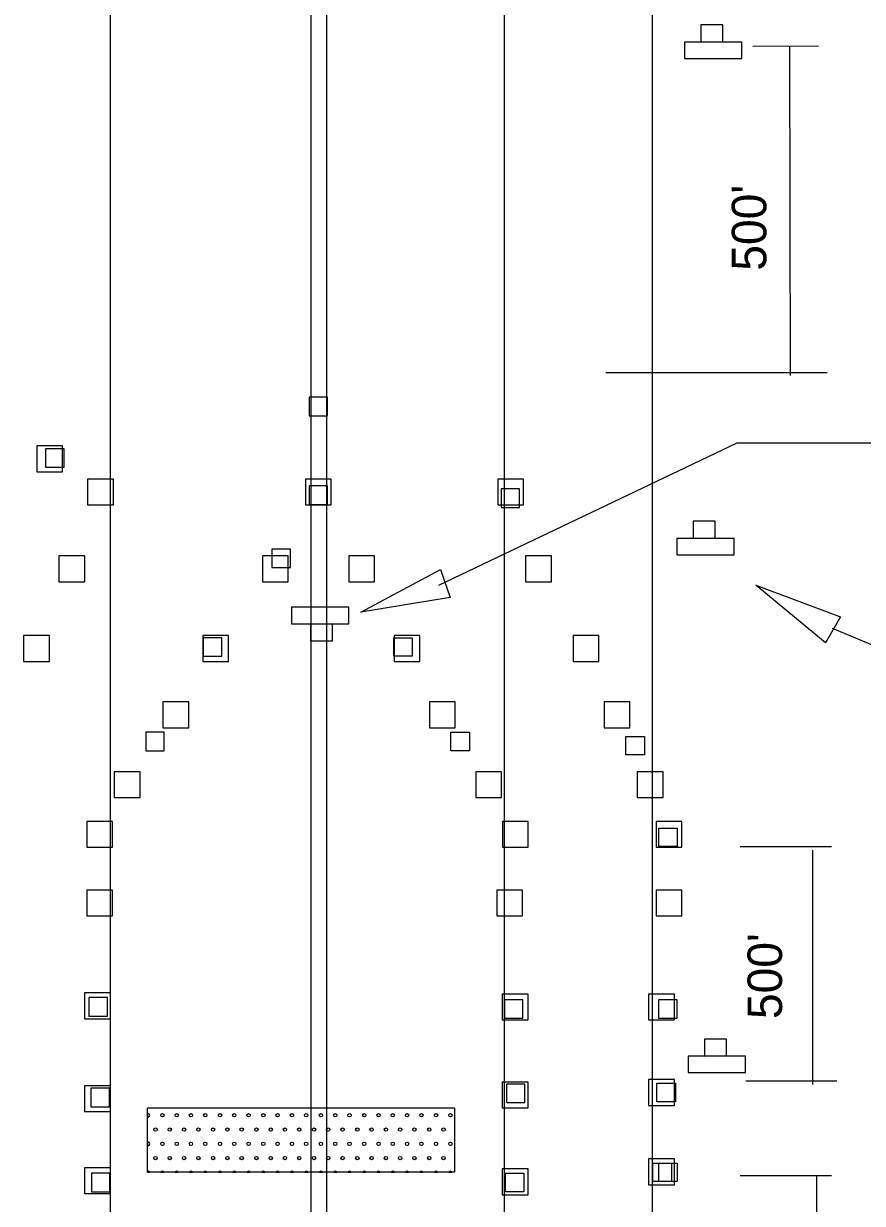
# Model space of a CAD drawing. Extents: x 1531.35 to 1538.58, y 1529.59 to 1539.23.
# Drawn here: x 1535.351 to 1536.808, y 1535.34 to 1537.39 of the extents above; entities that cross this region are included whole.
import ezdxf

# ---------------------------------------------------------------- set-up
doc = ezdxf.new("R2010")
doc.units = 0
for name, color, linetype in [('DETL-DIMS', 7, 'Continuous'), ('DETL-LINE', 7, 'Continuous'), ('DETL-NOTE', 7, 'Continuous'), ('USER-BORD', 7, 'Continuous')]:
    doc.layers.add(name, color=color, linetype=linetype)

# ---------------------------------------------------------------- blocks, each defined once
blk = doc.blocks.new('CD20')
at = {"layer": 'USER-BORD'}
blk.add_lwpolyline([(-0.0625, -0.0625), (0, -0.0625), (0, 0), (-0.0625, 0)], close=True, dxfattribs=at)
blk = doc.blocks.new('SIGN13')
at = {"layer": 'USER-BORD'}
for points in [[(-0.0134, 0.0182), (0.011, 0.0189), (0.011, 0.0371), (-0.0134, 0.0371)], [(-0.0314, 0.0182), (-0.0314, 0), (0.032, 0), (0.032, 0.0182)]]:
    blk.add_lwpolyline(points, close=True, dxfattribs=at)

msp = doc.modelspace()

# ---------------------------------------------------------------- linework, layer by layer
at = {"layer": 'DETL-DIMS'}
for p, q in [((1536.6173, 1537.3504), (1536.7316, 1537.3506)), ((1536.6829, 1536.7781), (1536.6818, 1537.3505)), ((1536.7465, 1536.7827), (1536.3621, 1536.7827)), ((1536.0721, 1536.4139), (1536.5902, 1536.6615)), ((1536.5902, 1536.6615), (1536.8925, 1536.6616)), ((1536.755, 1536.3393), (1537.0765, 1536.2049)), ((1536.5957, 1535.9605), (1536.7538, 1535.9605)), ((1536.7218, 1535.5467), (1536.7218, 1535.9538)), ((1536.6055, 1535.5534), (1536.7635, 1535.5534)), ((1536.5957, 1535.3886), (1536.7538, 1535.3886)), ((1536.7279, 1535.3886), (1536.7279, 1533.0756))]:
    msp.add_line(p, q, dxfattribs=at)
for points in [[(1536.0754, 1536.4414), (1536.0919, 1536.3925), (1535.9368, 1536.3672)], [(1536.7694, 1536.3589), (1536.7436, 1536.3141), (1536.6224, 1536.4141)]]:
    msp.add_lwpolyline(points, close=True, dxfattribs=at)
at = {"layer": 'DETL-LINE'}
for p, q in [((1536.1857, 1538.9058), (1536.1857, 1535.6352)), ((1535.5016, 1538.8924), (1535.5016, 1531.7496)), ((1535.8503, 1538.8924), (1535.8503, 1531.7496)), ((1535.8772, 1538.8924), (1535.8772, 1531.7496)), ((1536.4426, 1538.8924), (1536.4426, 1531.7496)), ((1536.1857, 1535.6352), (1536.1857, 1531.763)), ((1535.5667, 1535.3947), (1535.5667, 1535.5057)), ((1536.0994, 1535.5057), (1535.5667, 1535.5057)), ((1535.5667, 1535.3947), (1535.5667, 1535.5057)), ((1536.0994, 1535.5057), (1535.5667, 1535.5057)), ((1535.5676, 1535.4934), (1535.5676, 1535.4934)), ((1535.5924, 1535.4934), (1535.5924, 1535.4934)), ((1535.6172, 1535.4934), (1535.6172, 1535.4934)), ((1535.642, 1535.4934), (1535.642, 1535.4934)), ((1535.6668, 1535.4934), (1535.6668, 1535.4934)), ((1535.6924, 1535.4934), (1535.6924, 1535.4934)), ((1535.7172, 1535.4934), (1535.7172, 1535.4934)), ((1535.742, 1535.4934), (1535.742, 1535.4934)), ((1535.7676, 1535.4934), (1535.7676, 1535.4934)), ((1535.7924, 1535.4934), (1535.7924, 1535.4934)), ((1535.8172, 1535.4934), (1535.8172, 1535.4934)), ((1535.842, 1535.4934), (1535.842, 1535.4934)), ((1535.8676, 1535.4934), (1535.8676, 1535.4934)), ((1535.8924, 1535.4934), (1535.8924, 1535.4934)), ((1535.9172, 1535.4934), (1535.9172, 1535.4934)), ((1535.9428, 1535.4934), (1535.9428, 1535.4934)), ((1535.9676, 1535.4934), (1535.9676, 1535.4934)), ((1535.9924, 1535.4934), (1535.9924, 1535.4934)), ((1536.0172, 1535.4934), (1536.0172, 1535.4934)), ((1536.042, 1535.4934), (1536.042, 1535.4934)), ((1536.0676, 1535.4934), (1536.0676, 1535.4934)), ((1536.0924, 1535.4934), (1536.0924, 1535.4934)), ((1536.0994, 1535.5057), (1536.0994, 1535.3947)), ((1536.0994, 1535.5057), (1536.0994, 1535.3947)), ((1535.5796, 1535.4686), (1535.5796, 1535.4686)), ((1535.5804, 1535.4686), (1535.5804, 1535.4686)), ((1535.6044, 1535.4686), (1535.6044, 1535.4686)), ((1535.6052, 1535.4686), (1535.6052, 1535.4686)), ((1535.63, 1535.4686), (1535.63, 1535.4686)), ((1535.63, 1535.4686), (1535.63, 1535.4686)), ((1535.6548, 1535.4686), (1535.6548, 1535.4686)), ((1535.6548, 1535.4686), (1535.6548, 1535.4686)), ((1535.6796, 1535.4686), (1535.6796, 1535.4686)), ((1535.6804, 1535.4686), (1535.6804, 1535.4686)), ((1535.7044, 1535.4686), (1535.7044, 1535.4686)), ((1535.7052, 1535.4686), (1535.7052, 1535.4686)), ((1535.73, 1535.4686), (1535.73, 1535.4686)), ((1535.73, 1535.4686), (1535.73, 1535.4686)), ((1535.7548, 1535.4686), (1535.7548, 1535.4686)), ((1535.7556, 1535.4686), (1535.7556, 1535.4686)), ((1535.7796, 1535.4686), (1535.7796, 1535.4686)), ((1535.7804, 1535.4686), (1535.7804, 1535.4686)), ((1535.8044, 1535.4686), (1535.8044, 1535.4686)), ((1535.8052, 1535.4686), (1535.8052, 1535.4686)), ((1535.83, 1535.4686), (1535.83, 1535.4686)), ((1535.83, 1535.4686), (1535.83, 1535.4686)), ((1535.8548, 1535.4686), (1535.8548, 1535.4686)), ((1535.8556, 1535.4686), (1535.8556, 1535.4686)), ((1535.8796, 1535.4686), (1535.8796, 1535.4686)), ((1535.8804, 1535.4686), (1535.8804, 1535.4686)), ((1535.9052, 1535.4686), (1535.9052, 1535.4686)), ((1535.9052, 1535.4686), (1535.9052, 1535.4686)), ((1535.93, 1535.4686), (1535.93, 1535.4686)), ((1535.9308, 1535.4686), (1535.9308, 1535.4686)), ((1535.9548, 1535.4686), (1535.9548, 1535.4686)), ((1535.9556, 1535.4686), (1535.9556, 1535.4686)), ((1535.9796, 1535.4686), (1535.9796, 1535.4686)), ((1535.9804, 1535.4686), (1535.9804, 1535.4686)), ((1536.0052, 1535.4686), (1536.0052, 1535.4686)), ((1536.0052, 1535.4686), (1536.0052, 1535.4686)), ((1536.03, 1535.4686), (1536.03, 1535.4686)), ((1536.03, 1535.4686), (1536.03, 1535.4686)), ((1536.0548, 1535.4686), (1536.0548, 1535.4686)), ((1536.0556, 1535.4686), (1536.0556, 1535.4686)), ((1536.0796, 1535.4686), (1536.0796, 1535.4686)), ((1536.0804, 1535.4686), (1536.0804, 1535.4686)), ((1535.5676, 1535.4438), (1535.5676, 1535.4438)), ((1535.5676, 1535.4438), (1535.5676, 1535.4438)), ((1535.5924, 1535.4438), (1535.5924, 1535.4438)), ((1535.5924, 1535.4438), (1535.5924, 1535.4438)), ((1535.6172, 1535.4438), (1535.6172, 1535.4438)), ((1535.6172, 1535.4438), (1535.6172, 1535.4438)), ((1535.642, 1535.4438), (1535.642, 1535.4438)), ((1535.642, 1535.4438), (1535.642, 1535.4438)), ((1535.6668, 1535.4438), (1535.6668, 1535.4438)), ((1535.6668, 1535.4438), (1535.6668, 1535.4438)), ((1535.6924, 1535.4438), (1535.6924, 1535.4438)), ((1535.6924, 1535.4438), (1535.6924, 1535.4438)), ((1535.7172, 1535.4438), (1535.7172, 1535.4438)), ((1535.7172, 1535.4438), (1535.7172, 1535.4438)), ((1535.742, 1535.4438), (1535.742, 1535.4438)), ((1535.742, 1535.4438), (1535.742, 1535.4438)), ((1535.7676, 1535.4438), (1535.7676, 1535.4438)), ((1535.7676, 1535.4438), (1535.7676, 1535.4438)), ((1535.7924, 1535.4438), (1535.7924, 1535.4438)), ((1535.7924, 1535.4438), (1535.7924, 1535.4438)), ((1535.8172, 1535.4438), (1535.8172, 1535.4438)), ((1535.8172, 1535.4438), (1535.8172, 1535.4438)), ((1535.842, 1535.4438), (1535.842, 1535.4438)), ((1535.842, 1535.4438), (1535.842, 1535.4438)), ((1535.8676, 1535.4438), (1535.8676, 1535.4438)), ((1535.8676, 1535.4438), (1535.8676, 1535.4438)), ((1535.8924, 1535.4438), (1535.8924, 1535.4438)), ((1535.8924, 1535.4438), (1535.8924, 1535.4438)), ((1535.9172, 1535.4438), (1535.9172, 1535.4438)), ((1535.9172, 1535.4438), (1535.9172, 1535.4438)), ((1535.9428, 1535.4438), (1535.9428, 1535.4438)), ((1535.9428, 1535.4438), (1535.9428, 1535.4438)), ((1535.9676, 1535.4438), (1535.9676, 1535.4438)), ((1535.9676, 1535.4438), (1535.9676, 1535.4438)), ((1535.9924, 1535.4438), (1535.9924, 1535.4438)), ((1535.9924, 1535.4438), (1535.9924, 1535.4438)), ((1536.0172, 1535.4438), (1536.0172, 1535.4438)), ((1536.0172, 1535.4438), (1536.0172, 1535.4438)), ((1536.042, 1535.4438), (1536.042, 1535.4438)), ((1536.042, 1535.4438), (1536.042, 1535.4438)), ((1536.0676, 1535.4438), (1536.0676, 1535.4438)), ((1536.0676, 1535.4438), (1536.0676, 1535.4438)), ((1536.0924, 1535.4438), (1536.0924, 1535.4438)), ((1536.0924, 1535.4438), (1536.0924, 1535.4438)), ((1535.5796, 1535.419), (1535.5796, 1535.419)), ((1535.5804, 1535.419), (1535.5804, 1535.419)), ((1535.6044, 1535.419), (1535.6044, 1535.419)), ((1535.6052, 1535.419), (1535.6052, 1535.419)), ((1535.63, 1535.419), (1535.63, 1535.419)), ((1535.63, 1535.419), (1535.63, 1535.419)), ((1535.6548, 1535.419), (1535.6548, 1535.419)), ((1535.6548, 1535.419), (1535.6548, 1535.419)), ((1535.6796, 1535.419), (1535.6796, 1535.419)), ((1535.6804, 1535.419), (1535.6804, 1535.419)), ((1535.7044, 1535.419), (1535.7044, 1535.419)), ((1535.7052, 1535.419), (1535.7052, 1535.419)), ((1535.73, 1535.419), (1535.73, 1535.419)), ((1535.73, 1535.419), (1535.73, 1535.419)), ((1535.7548, 1535.419), (1535.7548, 1535.419)), ((1535.7556, 1535.419), (1535.7556, 1535.419)), ((1535.7796, 1535.419), (1535.7796, 1535.419)), ((1535.7804, 1535.419), (1535.7804, 1535.419)), ((1535.8044, 1535.419), (1535.8044, 1535.419)), ((1535.8052, 1535.419), (1535.8052, 1535.419)), ((1535.83, 1535.419), (1535.83, 1535.419)), ((1535.83, 1535.419), (1535.83, 1535.419)), ((1535.8548, 1535.419), (1535.8548, 1535.419)), ((1535.8556, 1535.419), (1535.8556, 1535.419)), ((1535.8796, 1535.419), (1535.8796, 1535.419)), ((1535.8804, 1535.419), (1535.8804, 1535.419)), ((1535.9052, 1535.419), (1535.9052, 1535.419)), ((1535.9052, 1535.419), (1535.9052, 1535.419)), ((1535.93, 1535.419), (1535.93, 1535.419)), ((1535.9308, 1535.419), (1535.9308, 1535.419)), ((1535.9548, 1535.419), (1535.9548, 1535.419)), ((1535.9556, 1535.419), (1535.9556, 1535.419)), ((1535.9796, 1535.419), (1535.9796, 1535.419)), ((1535.9804, 1535.419), (1535.9804, 1535.419)), ((1536.0052, 1535.419), (1536.0052, 1535.419)), ((1536.0052, 1535.419), (1536.0052, 1535.419)), ((1536.03, 1535.419), (1536.03, 1535.419)), ((1536.03, 1535.419), (1536.03, 1535.419)), ((1536.0548, 1535.419), (1536.0548, 1535.419)), ((1536.0556, 1535.419), (1536.0556, 1535.419)), ((1536.0796, 1535.419), (1536.0796, 1535.419)), ((1536.0804, 1535.419), (1536.0804, 1535.419)), ((1536.0994, 1535.3947), (1535.5667, 1535.3947)), ((1536.0994, 1535.3947), (1535.5667, 1535.3947))]:
    msp.add_line(p, q, dxfattribs=at)
for points in [[(1535.3743, 1536.6111), (1535.4191, 1536.6111), (1535.4191, 1536.6559), (1535.3743, 1536.6559)], [(1535.4626, 1536.5535), (1535.5074, 1536.5535), (1535.5074, 1536.5983), (1535.4626, 1536.5983)], [(1535.8407, 1536.5535), (1535.8855, 1536.5535), (1535.8855, 1536.5983), (1535.8407, 1536.5983)], [(1536.1747, 1536.5535), (1536.2195, 1536.5535), (1536.2195, 1536.5983), (1536.1747, 1536.5983)], [(1535.4128, 1536.4201), (1535.4576, 1536.4201), (1535.4576, 1536.4649), (1535.4128, 1536.4649)], [(1535.766, 1536.4201), (1535.8108, 1536.4201), (1535.8108, 1536.4649), (1535.766, 1536.4649)], [(1535.9158, 1536.4201), (1535.9606, 1536.4201), (1535.9606, 1536.4649), (1535.9158, 1536.4649)], [(1536.2229, 1536.4201), (1536.2677, 1536.4201), (1536.2677, 1536.4649), (1536.2229, 1536.4649)], [(1535.3514, 1536.2817), (1535.3962, 1536.2817), (1535.3962, 1536.3265), (1535.3514, 1536.3265)], [(1535.6624, 1536.2817), (1535.7072, 1536.2817), (1535.7072, 1536.3265), (1535.6624, 1536.3265)], [(1535.9945, 1536.2817), (1536.0393, 1536.2817), (1536.0393, 1536.3265), (1535.9945, 1536.3265)], [(1536.3054, 1536.2817), (1536.3502, 1536.2817), (1536.3502, 1536.3265), (1536.3054, 1536.3265)], [(1535.5933, 1536.1665), (1535.6381, 1536.1665), (1535.6381, 1536.2113), (1535.5933, 1536.2113)], [(1536.0559, 1536.1665), (1536.1007, 1536.1665), (1536.1007, 1536.2113), (1536.0559, 1536.2113)], [(1536.3592, 1536.1665), (1536.404, 1536.1665), (1536.404, 1536.2113), (1536.3592, 1536.2113)], [(1535.5088, 1536.0454), (1535.5536, 1536.0454), (1535.5536, 1536.0902), (1535.5088, 1536.0902)], [(1536.1365, 1536.0454), (1536.1813, 1536.0454), (1536.1813, 1536.0902), (1536.1365, 1536.0902)], [(1536.4168, 1536.0454), (1536.4616, 1536.0454), (1536.4616, 1536.0902), (1536.4168, 1536.0902)], [(1535.4609, 1535.9589), (1535.5057, 1535.9589), (1535.5057, 1536.0037), (1535.4609, 1536.0037)], [(1536.1826, 1535.9589), (1536.2274, 1535.9589), (1536.2274, 1536.0037), (1536.1826, 1536.0037)], [(1536.4494, 1535.9589), (1536.4942, 1535.9589), (1536.4942, 1536.0037), (1536.4494, 1536.0037)], [(1535.4609, 1535.8398), (1535.5057, 1535.8398), (1535.5057, 1535.8846), (1535.4609, 1535.8846)], [(1536.173, 1535.8398), (1536.2178, 1535.8398), (1536.2178, 1535.8846), (1536.173, 1535.8846)], [(1536.4494, 1535.8398), (1536.4942, 1535.8398), (1536.4942, 1535.8846), (1536.4494, 1535.8846)], [(1535.4572, 1535.6611), (1535.502, 1535.6611), (1535.502, 1535.7059), (1535.4572, 1535.7059)], [(1536.1824, 1535.659), (1536.2272, 1535.659), (1536.2272, 1535.7038), (1536.1824, 1535.7038)], [(1536.4364, 1535.659), (1536.4812, 1535.659), (1536.4812, 1535.7038), (1536.4364, 1535.7038)], [(1536.4364, 1535.5105), (1536.4812, 1535.5105), (1536.4812, 1535.5553), (1536.4364, 1535.5553)], [(1535.4572, 1535.4997), (1535.502, 1535.4997), (1535.502, 1535.5445), (1535.4572, 1535.5445)], [(1536.1824, 1535.5061), (1536.2272, 1535.5061), (1536.2272, 1535.5509), (1536.1824, 1535.5509)], [(1536.4364, 1535.3727), (1536.4812, 1535.3727), (1536.4812, 1535.4175), (1536.4364, 1535.4175)], [(1535.4572, 1535.3576), (1535.502, 1535.3576), (1535.502, 1535.4024), (1535.4572, 1535.4024)], [(1536.1824, 1535.3555), (1536.2272, 1535.3555), (1536.2272, 1535.4003), (1536.1824, 1535.4003)]]:
    msp.add_lwpolyline(points, close=True, dxfattribs=at)
for points in [[(1535.5667, 1535.4962), (1535.5667, 1535.4906)], [(1535.5667, 1535.4466), (1535.5667, 1535.441)], [(1535.5667, 1535.3961), (1535.5667, 1535.3947), (1535.5702, 1535.3947)], [(1535.5899, 1535.3947), (1535.595, 1535.3947)], [(1535.6147, 1535.3947), (1535.6198, 1535.3947)], [(1535.6395, 1535.3947), (1535.6446, 1535.3947)], [(1535.6643, 1535.3947), (1535.6694, 1535.3947)], [(1535.6899, 1535.3947), (1535.695, 1535.3947)], [(1535.7147, 1535.3947), (1535.7198, 1535.3947)], [(1535.7395, 1535.3947), (1535.7446, 1535.3947)], [(1535.7651, 1535.3947), (1535.7702, 1535.3947)], [(1535.7899, 1535.3947), (1535.795, 1535.3947)], [(1535.8147, 1535.3947), (1535.8198, 1535.3947)], [(1535.8395, 1535.3947), (1535.8446, 1535.3947)], [(1535.8651, 1535.3947), (1535.8702, 1535.3947)], [(1535.8899, 1535.3947), (1535.895, 1535.3947)], [(1535.9147, 1535.3947), (1535.9198, 1535.3947)], [(1535.9403, 1535.3947), (1535.9454, 1535.3947)], [(1535.9651, 1535.3947), (1535.9702, 1535.3947)], [(1535.9899, 1535.3947), (1535.995, 1535.3947)], [(1536.0147, 1535.3947), (1536.0198, 1535.3947)], [(1536.0395, 1535.3947), (1536.0446, 1535.3947)], [(1536.0651, 1535.3947), (1536.0702, 1535.3947)], [(1536.0899, 1535.3947), (1536.095, 1535.3947)]]:
    msp.add_lwpolyline(points, dxfattribs=at)
for centre in [(1535.5924, 1535.4934), (1535.6172, 1535.4934), (1535.642, 1535.4934), (1535.6668, 1535.4934), (1535.6924, 1535.4934), (1535.7172, 1535.4934), (1535.742, 1535.4934), (1535.7676, 1535.4934), (1535.7924, 1535.4934), (1535.8172, 1535.4934), (1535.842, 1535.4934), (1535.8676, 1535.4934), (1535.8924, 1535.4934), (1535.9172, 1535.4934), (1535.9428, 1535.4934), (1535.9676, 1535.4934), (1535.9924, 1535.4934), (1536.0172, 1535.4934), (1536.042, 1535.4934), (1536.0676, 1535.4934), (1536.0924, 1535.4934), (1535.5804, 1535.4686), (1535.6052, 1535.4686), (1535.63, 1535.4686), (1535.6548, 1535.4686), (1535.6804, 1535.4686), (1535.7052, 1535.4686), (1535.73, 1535.4686), (1535.7556, 1535.4686), (1535.7804, 1535.4686), (1535.8052, 1535.4686), (1535.83, 1535.4686), (1535.8556, 1535.4686), (1535.8804, 1535.4686), (1535.9052, 1535.4686), (1535.9308, 1535.4686), (1535.9556, 1535.4686), (1535.9804, 1535.4686), (1536.0052, 1535.4686), (1536.03, 1535.4686), (1536.0556, 1535.4686), (1536.0804, 1535.4686), (1535.5924, 1535.4438), (1535.6172, 1535.4438), (1535.642, 1535.4438), (1535.6668, 1535.4438), (1535.6924, 1535.4438), (1535.7172, 1535.4438), (1535.742, 1535.4438), (1535.7676, 1535.4438), (1535.7924, 1535.4438), (1535.8172, 1535.4438), (1535.842, 1535.4438), (1535.8676, 1535.4438), (1535.8924, 1535.4438), (1535.9172, 1535.4438), (1535.9428, 1535.4438), (1535.9676, 1535.4438), (1535.9924, 1535.4438), (1536.0172, 1535.4438), (1536.042, 1535.4438), (1536.0676, 1535.4438), (1536.0924, 1535.4438), (1535.5804, 1535.419), (1535.6052, 1535.419), (1535.63, 1535.419), (1535.6548, 1535.419), (1535.6804, 1535.419), (1535.7052, 1535.419), (1535.73, 1535.419), (1535.7556, 1535.419), (1535.7804, 1535.419), (1535.8052, 1535.419), (1535.83, 1535.419), (1535.8556, 1535.419), (1535.8804, 1535.419), (1535.9052, 1535.419), (1535.9308, 1535.419), (1535.9556, 1535.419), (1535.9804, 1535.419), (1536.0052, 1535.419), (1536.03, 1535.419), (1536.0556, 1535.419), (1536.0804, 1535.419)]:
    msp.add_circle(centre, 0.00291, dxfattribs=at)
for centre, start, end in [((1535.5676, 1535.4934), 251.7954, 108.2046), ((1535.5676, 1535.4438), 251.7954, 108.2046), ((1535.5676, 1535.3934), 27.8451, 108.2046), ((1535.5924, 1535.3934), 27.8451, 152.1549), ((1535.6172, 1535.3934), 27.8451, 152.1549), ((1535.642, 1535.3934), 27.8451, 152.1549), ((1535.6668, 1535.3934), 27.8451, 152.1549), ((1535.6924, 1535.3934), 27.8451, 152.1549), ((1535.7172, 1535.3934), 27.8451, 152.1549), ((1535.742, 1535.3934), 27.8451, 152.1549), ((1535.7676, 1535.3934), 27.8451, 152.1549), ((1535.7924, 1535.3934), 27.8451, 152.1549), ((1535.8172, 1535.3934), 27.8451, 152.1549), ((1535.842, 1535.3934), 27.8451, 152.1549), ((1535.8676, 1535.3934), 27.8451, 152.1549), ((1535.8924, 1535.3934), 27.8451, 152.1549), ((1535.9172, 1535.3934), 27.8451, 152.1549), ((1535.9428, 1535.3934), 27.8451, 152.1549), ((1535.9676, 1535.3934), 27.8451, 152.1549), ((1535.9924, 1535.3934), 27.8451, 152.1549), ((1536.0172, 1535.3934), 27.8451, 152.1549), ((1536.042, 1535.3934), 27.8451, 152.1549), ((1536.0676, 1535.3934), 27.8451, 152.1549), ((1536.0924, 1535.3934), 27.8451, 152.1549)]:
    msp.add_arc(centre, 0.00291, start, end, dxfattribs=at)

# ---------------------------------------------------------------- block references
for name, p, xscale, yscale in [('SIGN13', (1536.5481, 1537.3289), 1.568744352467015, 1.5687443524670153), ('CD20', (1535.8793, 1536.7405), 0.5153677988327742, 0.5153677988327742), ('CD20', (1535.4217, 1536.6511), 0.5153677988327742, 0.5153677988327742), ('CD20', (1535.4217, 1536.6511), 0.5153677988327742, 0.5153677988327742), ('CD20', (1535.8793, 1536.5864), 0.5153677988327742, 0.5153677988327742), ('CD20', (1535.8793, 1536.5864), 0.5153677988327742, 0.5153677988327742), ('CD20', (1535.8793, 1536.5864), 0.5153677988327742, 0.5153677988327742), ('CD20', (1536.2125, 1536.5814), 0.5153677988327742, 0.5153677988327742), ('SIGN13', (1536.5347, 1536.4669), 1.568744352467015, 1.5687443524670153), ('CD20', (1535.8146, 1536.4769), 0.5153677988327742, 0.5153677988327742), ('CD20', (1535.8146, 1536.4769), 0.5153677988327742, 0.5153677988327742), ('CD20', (1535.6953, 1536.3228), 0.5153677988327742, 0.5153677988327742), ('CD20', (1535.6953, 1536.3228), 0.5153677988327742, 0.5153677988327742), ('CD20', (1535.5957, 1536.1587), 0.5153677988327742, 0.5153677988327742), ('CD20', (1535.5957, 1536.1587), 0.5153677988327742, 0.5153677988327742), ('CD20', (1535.5957, 1536.1587), 0.5153677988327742, 0.5153677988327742), ('CD20', (1535.4968, 1535.6977), 0.5153677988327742, 0.5153677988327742), ('CD20', (1536.2183, 1535.6941), 0.5153677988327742, 0.5153677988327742), ('CD20', (1536.4861, 1535.6941), 0.5153677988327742, 0.5153677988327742), ('SIGN13', (1536.5545, 1535.5675), 1.568744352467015, 1.5687443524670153), ('CD20', (1535.5004, 1535.5405), 0.5153677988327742, 0.5153677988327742), ('CD20', (1536.2218, 1535.5477), 0.5153677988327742, 0.5153677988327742), ('CD20', (1535.5013, 1535.3926), 0.5153677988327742, 0.5153677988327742), ('CD20', (1535.5013, 1535.3926), 0.5153677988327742, 0.5153677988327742), ('CD20', (1535.5013, 1535.3926), 0.5153677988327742, 0.5153677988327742)]:
    msp.add_blockref(name, p, dxfattribs=dict(at, xscale=xscale, yscale=yscale))
for name, p, xscale, yscale, rotation in [('SIGN13', (1535.8667, 1536.3757), 1.568744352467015, 1.5687443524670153, 179.99999999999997), ('CD20', (1535.9939, 1536.3228), 0.5153677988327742, -0.5153677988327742, 180), ('CD20', (1536.0934, 1536.1587), 0.5153677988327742, -0.5153677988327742, 180), ('CD20', (1536.0934, 1536.1587), 0.5153677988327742, -0.5153677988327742, 180), ('CD20', (1536.0934, 1536.1587), 0.5153677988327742, -0.5153677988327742, 180), ('CD20', (1536.3969, 1536.1515), 0.5153677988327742, -0.5153677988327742, 180), ('CD20', (1536.4541, 1535.9923), 0.5153677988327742, -0.5153677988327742, 180), ('CD20', (1536.4509, 1535.5489), 0.5153677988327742, -0.5153677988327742, 180), ('CD20', (1536.444, 1535.4104), 0.5153677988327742, -0.5153677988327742, 180), ('CD20', (1536.4541, 1535.4104), 0.5153677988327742, -0.5153677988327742, 180), ('CD20', (1536.4541, 1535.4104), 0.5153677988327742, -0.5153677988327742, 180), ('CD20', (1536.1879, 1535.3926), 0.5153677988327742, -0.5153677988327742, 180), ('CD20', (1536.1879, 1535.3926), 0.5153677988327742, -0.5153677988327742, 180), ('CD20', (1536.1879, 1535.3926), 0.5153677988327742, -0.5153677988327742, 180)]:
    msp.add_blockref(name, p, dxfattribs=dict(at, xscale=xscale, yscale=yscale, rotation=rotation))

# ---------------------------------------------------------------- texts
at = {"layer": 'DETL-NOTE'}
for p in [(1536.6409, 1536.9603), (1536.6682, 1535.6605)]:
    msp.add_text("500'", height=0.06, rotation=90, dxfattribs=at).set_placement(p)

doc.saveas('drawing.dxf')
